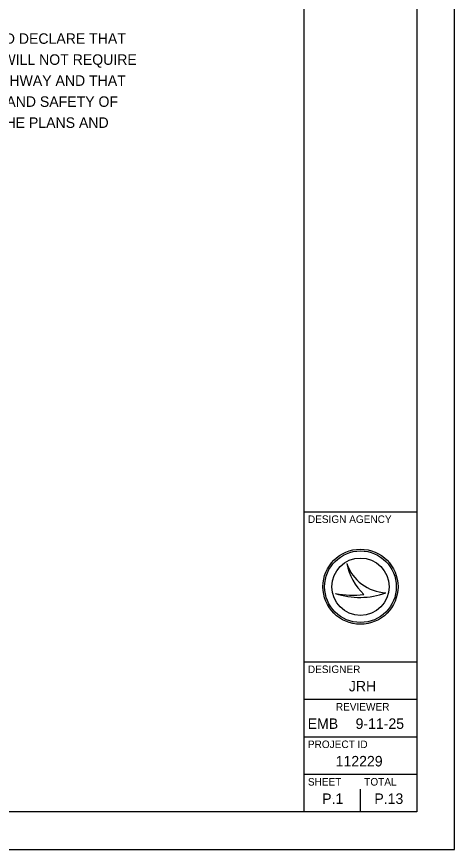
# Model space of a CAD drawing. Extents: x 0 to 34, y 0 to 22.
# Drawn here: x 28.17 to 34, y 0 to 11.1 of the extents above; entities that cross this region are included whole.
import ezdxf

# ---------------------------------------------------------------- set-up
doc = ezdxf.new("R2010")
doc.units = 0
for name, color, linetype in [('Default', 7, 'Continuous'), ('SH_Border', 7, 'Continuous'), ('SH_Cut_Line', 7, 'Continuous'), ('SH_Data', 7, 'Continuous')]:
    doc.layers.add(name, color=color, linetype=linetype)

msp = doc.modelspace()

# ---------------------------------------------------------------- linework, layer by layer
at = {"layer": 'SH_Border'}
for p, q in [((32, 0.5), (32, 21.5)), ((32, 4.5), (33.5, 4.5)), ((32, 2.5), (33.5, 2.5)), ((32, 2), (33.5, 2)), ((32, 1.5), (33.5, 1.5)), ((32, 1), (33.5, 1))]:
    msp.add_line(p, q, dxfattribs=at)
msp.add_lwpolyline([(1.5, 21.5), (33.5, 21.5), (33.5, 0.5), (1.5, 0.5)], close=True, dxfattribs=at)
at = {"layer": 'SH_Cut_Line'}
msp.add_lwpolyline([(0, 0), (34, 0), (34, 22), (0, 22)], close=True, dxfattribs=at)
at = {"layer": 'SH_Data'}
for p, q in [((32.567, 3.81), (32.567, 3.81)), ((32.75, 3.5), (32.75, 3.5)), ((32.417, 3.41), (32.417, 3.41)), ((33.087, 3.419), (33.087, 3.419)), ((32.75, 0.5), (32.75, 0.8)), ((32.375, 0.675), (32.375, 0.675))]:
    msp.add_line(p, q, dxfattribs=at)
for radius in [0.5, 0.477, 0.477, 0.382]:
    msp.add_circle((32.75, 3.5), radius, dxfattribs=at)
for centre, radius, start, end in [((33.116, 3.998), 0.58, 198.9257, 198.9319), ((33.347, 3.97), 0.796, 191.6379, 191.6421), ((33.116, 3.998), 0.58, 198.9319, 267.1657), ((33.347, 3.97), 0.796, 191.6421, 226.0947), ((32.739, 4.37), 1.013, 251.4576, 290.0832), ((32.648, 4.654), 1.266, 259.4964, 259.4995), ((32.739, 4.37), 1.013, 251.4527, 251.4576), ((32.648, 4.654), 1.266, 259.4995, 276.6672)]:
    msp.add_arc(centre, radius, start, end, dxfattribs=at)

# ---------------------------------------------------------------- texts
at = {"layer": 'Default'}
for s, p in [('I HEREBY APPROVE THESE PLANS AND DECLARE THAT', (24.528, 10.735)), ('THE MAKING OF THIS IMPROVEMENT WILL NOT REQUIRE', (24.528, 10.455)), ('THE CLOSING TO TRAFFIC TO THE HIGHWAY AND THAT', (24.528, 10.175)), ('PROVISIONS FOR THE MAINTENANCE AND SAFETY OF ', (24.528, 9.895)), ('TRAFFIC WILL BE AS SET FORTH ON THE PLANS AND', (24.528, 9.615))]:
    msp.add_text(s, height=0.14, dxfattribs=at).set_placement(p)
at = {"layer": 'SH_Data'}
for s, height, p in [('DESIGN AGENCY', 0.1, (32.05, 4.35)), ('DESIGNER', 0.1, (32.05, 2.35)), ('JRH', 0.14, (32.595, 2.105)), ('REVIEWER', 0.1, (32.422, 1.85)), ('EMB', 0.14, (32.047, 1.605)), ('9-11-25', 0.14, (32.685, 1.605)), ('PROJECT ID', 0.1, (32.05, 1.35)), ('112229', 0.14, (32.42, 1.105)), ('SHEET', 0.1, (32.05, 0.85)), ('TOTAL', 0.1, (32.8, 0.85)), ('P.1', 0.14, (32.24, 0.605)), ('P.13', 0.14, (32.935, 0.605))]:
    msp.add_text(s, height=height, dxfattribs=at).set_placement(p)

doc.saveas('drawing.dxf')
